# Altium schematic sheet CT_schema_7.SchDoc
size 147 x 119 mm
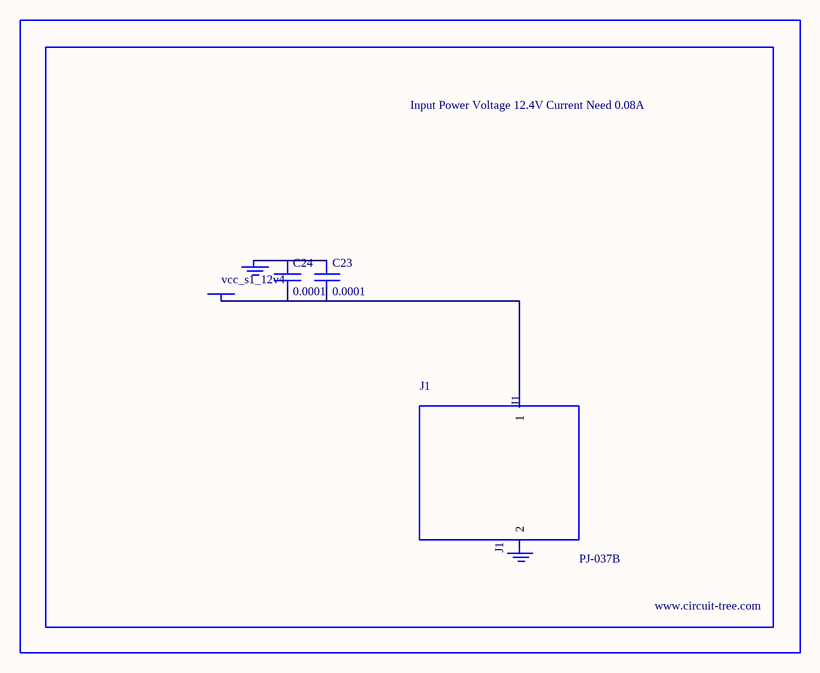
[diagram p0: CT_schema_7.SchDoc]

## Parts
BORDER6  (no value)
C23  0.0001  [EXV-9H]
C24  0.0001  [EXV-9H]
GND_INSTANCE_6_0  (no value)
GND_INSTANCE_6_1  (no value)
J1  PJ-037B  [PJ-037B_PACKAGE]
POWER_INSTANCE_6_0  vcc_s1_12v4

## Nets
NetC23_1: C23.1 C24.1 GND_INSTANCE_6_0.0(GND)
NetC23_2: C23.2 C24.2 J1.1 POWER_INSTANCE_6_0.0(PWR)

Not connected (* = marked no-connect by the designer): GND_INSTANCE_6_1 0(GND); J1 2

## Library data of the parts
BORDER6 = BORDER_PAGE6
C23 C24 = EDK107M035A9HAA
GND_INSTANCE_6_0 GND_INSTANCE_6_1 = GND
POWER_INSTANCE_6_0 = PWR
